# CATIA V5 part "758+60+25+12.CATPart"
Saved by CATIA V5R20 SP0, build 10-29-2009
Part number: 758+60+25+12
Revision: TUTTO
Definition: NON CONOSCIUTO
Nomenclature: 758+60+25+12
Source: Unknown
Bounding box of the stored display mesh (mm): x -30 to 30, y 0 to 25, z -30 to 30
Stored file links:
  C:\Users\Utente\Desktop\IO LAVORO\3D X SITO CF\X 3D SITO CF 27-09-2020\758\758+60+25+12.CATPart
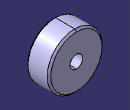
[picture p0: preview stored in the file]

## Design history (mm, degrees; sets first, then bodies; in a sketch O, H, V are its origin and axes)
Body1 "Smusso 2x45°" (main body)
  Solid1: solid without history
